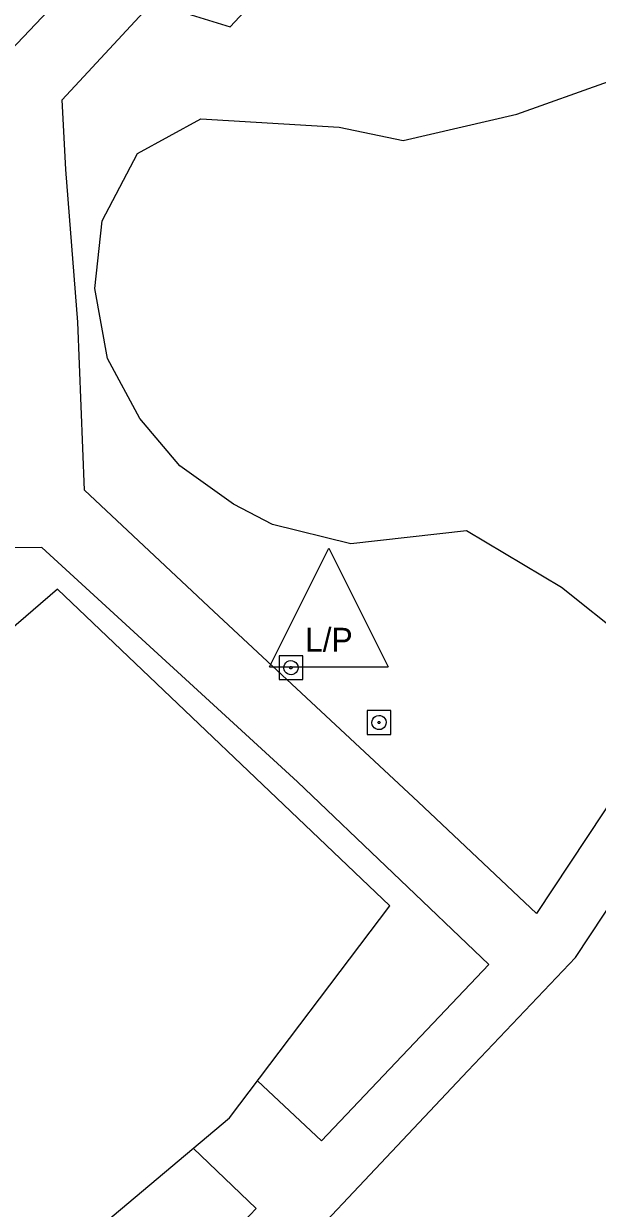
# Model space of a CAD drawing. Extents: x 2161152 to 2175754, y 602179 to 617749.
# Drawn here: x 2163463.8 to 2163512.2, y 605235.6 to 605335.5 of the extents above; entities that cross this region are included whole.
import ezdxf

# ---------------------------------------------------------------- set-up
doc = ezdxf.new("R2010")
doc.units = 0
for name, color, linetype in [('RD_EX_Bldg', 7, 'Continuous'), ('RD_EX_Conc_Sidewalk', 7, 'Continuous'), ('RD_EX_Misc', 7, 'Continuous'), ('RD_EX_UT', 7, 'Continuous'), ('RD_EX_VEG', 7, 'Continuous')]:
    doc.layers.add(name, color=color, linetype=linetype)

msp = doc.modelspace()

# ---------------------------------------------------------------- linework, layer by layer
at = {"layer": 'RD_EX_Bldg'}
msp.add_lwpolyline([(2163464.053, 605228.799), (2163481.192, 605243.237), (2163494.713, 605261.116), (2163466.679, 605287.8), (2163449.611, 605273.104), (2163435.957, 605255.267), (2163464.053, 605228.799)], dxfattribs=at)
at = {"layer": 'RD_EX_Conc_Sidewalk'}
for points in [[(2163481.818, 605353.479), (2163479.13, 605350.555), (2163471.137, 605342.131), (2163462.755, 605333.284), (2163458.247, 605328.591), (2163457.155, 605327.778), (2163455.876, 605327.31), (2163454.517, 605327.226), (2163453.19, 605327.531), (2163452.006, 605328.202), (2163451.779, 605328.39), (2163449.003, 605331.139), (2163445.315, 605335.037), (2163442.559, 605337.897)], [(2163521.188, 605281.757), (2163507.086, 605260.461), (2163497.1, 605269.875), (2163479.881, 605285.936), (2163468.954, 605296.15), (2163468.397, 605310.321), (2163467.396, 605323.214), (2163467.09, 605329.077), (2163474.679, 605337.271), (2163481.245, 605335.237), (2163484.001, 605338.207), (2163485.277, 605339.619), (2163486.816, 605340.739), (2163488.552, 605341.518), (2163490.411, 605341.924), (2163492.314, 605341.939), (2163492.769, 605341.884), (2163498.893, 605340.559), (2163502.788, 605345.389), (2163517.966, 605341.741)], [(2163483.545, 605246.347), (2163488.936, 605241.29), (2163503.052, 605256.152), (2163486.934, 605271.562), (2163465.369, 605291.324), (2163448.874, 605291.127), (2163449.278, 605280.862), (2163449.491, 605279.554), (2163450.078, 605278.365), (2163450.894, 605277.473), (2163452.728, 605275.788)], [(2163479.719, 605224.295), (2163501.277, 605247.175), (2163510.37, 605256.746), (2163522.569, 605275.202)], [(2163456.809, 605235.623), (2163455.59, 605234.304), (2163469.547, 605220.951), (2163483.442, 605235.568), (2163478.13, 605240.657)]]:
    msp.add_lwpolyline(points, dxfattribs=at)
at = {"layer": 'RD_EX_Misc'}
for points in [[(2163485.368, 605280.191), (2163487.368, 605280.191), (2163487.368, 605282.191), (2163485.368, 605282.191), (2163485.368, 605280.191)], [(2163485.768, 605281.191), (2163485.788, 605281.343), (2163485.845, 605281.485), (2163485.937, 605281.608), (2163486.057, 605281.704), (2163486.197, 605281.766), (2163486.349, 605281.791), (2163486.502, 605281.776), (2163486.646, 605281.723), (2163486.772, 605281.635), (2163486.871, 605281.518), (2163486.938, 605281.38), (2163486.967, 605281.229), (2163486.968, 605281.191)], [(2163486.968, 605281.191), (2163486.948, 605281.039), (2163486.891, 605280.897), (2163486.799, 605280.774), (2163486.679, 605280.678), (2163486.539, 605280.616), (2163486.387, 605280.591), (2163486.234, 605280.606), (2163486.09, 605280.659), (2163485.964, 605280.747), (2163485.865, 605280.864), (2163485.798, 605281.002), (2163485.769, 605281.153), (2163485.768, 605281.191)], [(2163486.268, 605281.191), (2163486.287, 605281.25), (2163486.337, 605281.286), (2163486.399, 605281.286), (2163486.449, 605281.25), (2163486.468, 605281.191)], [(2163486.468, 605281.191), (2163486.449, 605281.132), (2163486.399, 605281.096), (2163486.337, 605281.096), (2163486.287, 605281.132), (2163486.268, 605281.191)], [(2163492.796, 605275.565), (2163494.796, 605275.565), (2163494.796, 605277.565), (2163492.796, 605277.565), (2163492.796, 605275.565)], [(2163493.196, 605276.565), (2163493.216, 605276.717), (2163493.273, 605276.859), (2163493.365, 605276.982), (2163493.485, 605277.078), (2163493.625, 605277.14), (2163493.777, 605277.165), (2163493.93, 605277.15), (2163494.074, 605277.097), (2163494.2, 605277.009), (2163494.299, 605276.892), (2163494.366, 605276.754), (2163494.395, 605276.603), (2163494.396, 605276.565)], [(2163494.396, 605276.565), (2163494.376, 605276.413), (2163494.319, 605276.271), (2163494.227, 605276.148), (2163494.107, 605276.052), (2163493.967, 605275.99), (2163493.815, 605275.965), (2163493.662, 605275.98), (2163493.518, 605276.033), (2163493.392, 605276.121), (2163493.293, 605276.238), (2163493.226, 605276.376), (2163493.197, 605276.527), (2163493.196, 605276.565)], [(2163493.696, 605276.565), (2163493.715, 605276.624), (2163493.765, 605276.66), (2163493.827, 605276.66), (2163493.877, 605276.624), (2163493.896, 605276.565)], [(2163493.896, 605276.565), (2163493.877, 605276.506), (2163493.827, 605276.47), (2163493.765, 605276.47), (2163493.715, 605276.506), (2163493.696, 605276.565)]]:
    msp.add_lwpolyline(points, dxfattribs=at)
at = {"layer": 'RD_EX_UT'}
for p, q in [((2163484.572, 605281.269), (2163489.572, 605291.269)), ((2163489.572, 605291.269), (2163494.572, 605281.269)), ((2163484.572, 605281.269), (2163494.572, 605281.269))]:
    msp.add_line(p, q, dxfattribs=at)
at = {"layer": 'RD_EX_VEG'}
msp.add_lwpolyline([(2163514.6, 605283.625), (2163509.183, 605287.95), (2163501.159, 605292.74), (2163491.417, 605291.648), (2163484.801, 605293.274), (2163481.537, 605294.991), (2163477.014, 605298.212), (2163473.633, 605302.211), (2163470.896, 605307.269), (2163469.841, 605313.163), (2163470.439, 605318.891), (2163473.425, 605324.547), (2163478.758, 605327.471), (2163490.423, 605326.772), (2163495.828, 605325.645), (2163505.422, 605327.862), (2163513.143, 605330.638)], dxfattribs=at)

# ---------------------------------------------------------------- texts
at = {"layer": 'RD_EX_UT'}
msp.add_text('L/P', height=2, dxfattribs=at).set_placement((2163487.563, 605282.551))

doc.saveas('drawing.dxf')
